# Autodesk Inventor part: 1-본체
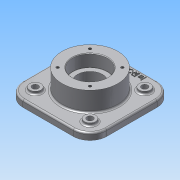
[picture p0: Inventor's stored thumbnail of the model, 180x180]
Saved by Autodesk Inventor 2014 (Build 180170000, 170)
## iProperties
Created: 2015-09
Part Number: 1-본체
Material: 알루미늄 6061
Document SubType Name: Modeling
Designer: study
Density: 2.71 g/cm^3
Appearance: 알루미늄 - 평지
Mass: 1463.03 g
Surface Area: 804.535 cm^2
Volume: 539.862 cm^3
Author: study
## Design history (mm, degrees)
sketch "스케치1"
  geometry: L1 (-75, 75)-(75, 75); L2 (75, 75)-(75, -75); L3 (75, -75)-(-75, -75); L4 (-75, -75)-(-75, 75); L5 (-75, 75)-(75, -75); L6 (75, 75)-(-75, -75); 1 further point
  constraints: 12 end point, 2 midpoint, 2 parallel, 1 horizontal, 1 perpendicular
  dimensions: "d0" = 150 distance of L1.start L1.end; "d1" = 150 distance of L1.end L2.end
extrude "돌출1" new body sketch "스케치1" distance "d2" = 12; taper "d3" = 0 deg
fillet "모깎기1" dims "d4" = 30
sketch "스케치2"
  geometry: C1 r 50 at (0, 0); 1 further point
  constraints: 1 centre point, 1 coincident
  dimensions: "d5" = 100 diameter of C1
extrude "돌출2" join sketch "스케치2" distance "d6" = 35; taper "d7" = 0 deg
sketch "스케치3"
  geometry: C1 r 50 at (0, 0) reference; 1 further point
extrude "돌출3" join sketch "스케치3" distance "d8" = 23; taper "d9" = 0 deg
hole "구멍1" diameter "d12" = 45; stored, may be unused: countersink angle "d16" = 90 deg, drill point angle "d18" = 118 deg; dims "d10" = 10, "d11" = 10, "d13" = 6, "d14" = 62, "d15" = 22, "d17" = 8
hole "구멍2" diameter "d21" = 45; stored, may be unused: countersink angle "d25" = 90 deg, drill point angle "d27" = 118 deg; dims "d19" = 10, "d20" = 10, "d22" = 6, "d23" = 62, "d24" = 22, "d26" = 8
sketch "스케치4"
  geometry: C1 r 50 at (0, 0) reference; C2 r 10 at (-49, -49); C3 r 10 at (49, -49); C4 r 10 at (49, 49); C5 r 10 at (-49, 49); C6 r 5.5 at (-49, 49); C7 r 5.5 at (-49, -49); C8 r 5.5 at (49, -49); C9 r 5.5 at (49, 49)
  constraints: 8 centre point, 4 coincident, 2 horizontal alignment, 2 vertical alignment, 1 equal radius
  dimensions: "d31" = 49 horizontal distance of C2.centre C1.centre; "d33" = 98 distance of C5.centre C4.centre; "d34" = 49 horizontal distance of C1.centre C4.centre; "d35" = 98 distance of C2.centre C5.centre; "d36" = 20 diameter of C5; "d37" = 20 diameter of C4; "d38" = 20 diameter of C2; "d41" = 11 diameter of C9; "d42" = 11 diameter of C8; "d43" = 11 diameter of C7; "d44" = 11 diameter of C6
extrude "돌출4" join sketch "스케치4" distance "d39" = 5; taper "d40" = 0 deg
extrude "돌출5" cut sketch "스케치4" stored distance "d45" = 30; taper "d46" = 0 deg
sketch "스케치5"
  geometry: L1 (-28.991, 28.991)-(28.991, 28.991); L2 (28.991, 28.991)-(28.991, -28.991); L3 (28.991, -28.991)-(-28.991, -28.991); L4 (-28.991, -28.991)-(-28.991, 28.991); L5 (-28.991, 28.991)-(28.991, -28.991); L6 (28.991, 28.991)-(-28.991, -28.991); C1 r 50 at (0, 0) reference; 4 further points
  constraints: 12 end point, 4 coincident, 2 midpoint, 2 parallel, 2 perpendicular, 1 horizontal
  dimensions: "d47" = 82 distance of L2.end L1.start
hole "구멍3" sketch "스케치5" at (-28.991, 28.991), (28.991, 28.991), (28.991, -28.991), (-28.991, -28.991) diameter "d48" = 4.917; stored, may be unused: countersink angle "d52" = 90 deg, drill point angle "d54" = 118 deg; dims "d49" = 10, "d50" = 4, "d51" = 2, "d53" = 13
node "작업 평면1"
sketch "스케치6"
  geometry: C1 r 50 at (0, 0) reference; 1 further point
  constraints: 1 vertical alignment, 1 other
  dimensions: "d55" = 65 distance of C1.centre point (0, 65)
feature "엠보싱1" sketch "스케치6" dims "d0" = 150, "d1" = 150, "d15" = 22, "d56" = 1, "d57" = 0
chamfer "모따기1" distance "d58" = 1; stored, may be unused: second distance "d59" = 2, angle "d60" = 45 deg
fillet "모깎기2" dims "d61" = 3, "d62" = 0.3, "d63" = 3
node "솔리드1"
mirror "대칭1"
